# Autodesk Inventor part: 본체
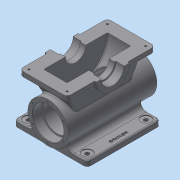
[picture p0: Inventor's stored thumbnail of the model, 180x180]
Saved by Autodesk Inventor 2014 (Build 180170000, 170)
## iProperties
Created: 2023-07
Part Number: 본체
Material: 일반
Document SubType Name: Modeling
Designer: dg
Density: 1 g/cm^3
Appearance: 기본값
Author: dg
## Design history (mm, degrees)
sketch "스케치1"
  geometry: L1 (-121, 0)-(121, 0); L2 (-121, 0)-(-121, 55); L3 (-121, 55)-(121, 55); L4 (121, 55)-(121, 0); L5 (-121, 42.5)-(-96, 42.5); L6 (-96, 42.5)-(-96, 38.5); L7 (-96, 38.5)-(96, 38.5); L8 (96, 38.5)-(96, 42.5); L9 (96, 42.5)-(121, 42.5); 2 further points
  constraints: 18 end point, 5 perpendicular, 3 parallel, 2 coincident, 2 point on line, 1 horizontal, 1 midpoint
  dimensions: "d0" = 242 distance of L1.start L1.end; "d1" = 110 diameter of L3 L1; "d2" = 85 diameter of L5 L1; "d3" = 77 diameter of L7 L1; "d4" = 85 diameter of L9 L1; "d5" = 25 distance between parallel lines of L4 L8; "d6" = 25 distance between parallel lines of L2 L6
revolve "회전1" sketch "스케치1" stored, may be unused: angle "d7" = 90 deg
node "작업 평면1"
sketch "스케치2"
  geometry: L1 (-100, -45)-(100, -45); L2 (100, -45)-(100, -60); L3 (100, -60)-(-100, -60); L4 (-100, -60)-(-100, -45); 2 further points
  constraints: 8 end point, 2 parallel, 1 horizontal, 1 midpoint, 1 perpendicular, 1 vertical alignment
  dimensions: "d9" = 60 distance from line of L3 point (0, 0); "d10" = 15 distance between parallel lines of L3 L1; "d11" = 200 distance between parallel lines of L2 L4
extrude "돌출1" join sketch "스케치2" stored distance "d12" = 200; taper "d13" = 0 deg
fillet "모깎기1" dims "d14" = 15
sketch "스케치3"
  geometry: L1 (-114, -60)-(86, -60) reference; L2 (-121, -55)-(-121, 55) reference; L3 (-114, 100)-(86, 100); L4 (86, -55)-(86, -60) reference; L5 (86, -60)-(-114, -60) reference; L6 (-114, -60)-(-114, -55) reference; L7 (-114, -55)-(-121, -55) reference; L8 (-121, -55)-(-121, -42.5) reference; L9 (-121, -42.5)-(-96, -42.5) reference; L10 (-96, -42.5)-(-96, -38.5) reference; L11 (-96, -38.5)-(96, -38.5) reference; L12 (96, -38.5)-(96, -42.5) reference; L13 (96, -42.5)-(121, -42.5) reference; L14 (121, -42.5)-(121, -55) reference; L15 (121, -55)-(86, -55) reference; L16 (-121, 55)-(121, 55) reference; L17 (121, 55)-(121, 42.5) reference; L18 (121, 42.5)-(96, 42.5) reference; L19 (96, 42.5)-(96, 38.5) reference; L20 (96, 38.5)-(-96, 38.5) reference; L21 (-96, 38.5)-(-96, 42.5) reference; L22 (-96, 42.5)-(-121, 42.5) reference; L23 (-121, 42.5)-(-121, 55) reference; A1 r 100 centre (-14, 100) between (-114, 100) and (86, 100); 2 further points
  constraints: 2 end point, 2 point on circle, 1 centre point, 1 coincident, 1 midpoint, 1 perpendicular
  dimensions: "d15" = 200 diameter of A1; "d16" = 160 distance from line of L1 A1.centre; "d17" = 107 distance from line of L2 A1.centre
extrude "돌출2" join sketch "스케치3" stored distance "d18" = 90; taper "d19" = 0 deg
sketch "스케치4"
  geometry: L1 (90, 200)-(90, 0) reference; L2 (0, 200)-(90, 200) reference; L3 (-20, 220)-(110, 220); L4 (110, 220)-(110, -20); L5 (110, -20)-(-20, -20); L6 (-20, -20)-(-20, 220); 5 further points
  constraints: 8 end point, 4 midpoint, 2 parallel, 1 horizontal, 1 horizontal alignment, 1 perpendicular, 1 vertical alignment
  dimensions: "d20" = 130 distance between parallel lines of L4 L6; "d21" = 240 distance between parallel lines of L5 L3
extrude "돌출3" join sketch "스케치4" distance "d22" = 15; taper "d23" = 0 deg
sketch "스케치5"
  geometry: L1 (-92.853, 38.5)-(-96, 38.5) reference; L2 (-96, 38.5)-(-96, 42.5) reference; L3 (-96, 42.5)-(-121, 42.5) reference; L4 (-121, 42.5)-(-121, 55) reference; L5 (-121, 55)-(-103.303, 55) reference; L6 (-112.869, 85)-(-134, 85) reference; L7 (-134, 85)-(-134, 100) reference; L8 (-134, 100)-(106, 100) reference; L9 (106, 100)-(106, 85) reference; L10 (106, 85)-(84.869, 85) reference; L11 (75.303, 55)-(121, 55) reference; L12 (121, 55)-(121, 42.5) reference; L13 (121, 42.5)-(96, 42.5) reference; L14 (96, 42.5)-(96, 38.5) reference; L15 (96, 38.5)-(64.853, 38.5) reference; L16 (86, -55)-(86, -60) reference; L17 (86, -60)-(-114, -60) reference; L18 (-114, -60)-(-114, -55) reference; L19 (-114, -55)-(-121, -55) reference; L20 (-121, -55)-(-121, -42.5) reference; L21 (-121, -42.5)-(-96, -42.5) reference; L22 (-96, -42.5)-(-96, -38.5) reference; L23 (-96, -38.5)-(96, -38.5) reference; L24 (96, -38.5)-(96, -42.5) reference; L25 (96, -42.5)-(121, -42.5) reference; L26 (121, -42.5)-(121, -55) reference; L27 (121, -55)-(86, -55) reference; C1 r 87 at (-14, 100); A1 r 100 centre (-14, 100) between (-92.853, 38.5) and (64.853, 38.5) reference; A2 r 100 centre (-14, 100) between (-112.869, 85) and (-103.303, 55) reference; A3 r 100 centre (-14, 100) between (75.303, 55) and (84.869, 85) reference; 1 further point
  constraints: 1 centre point, 1 coincident
  dimensions: "d24" = 87 radius of C1
  node "절단 모서리 투영2"
extrude "돌출4" cut sketch "스케치5" stored distance "d25" = 64; taper "d26" = 0 deg
sketch "스케치6"
  geometry: C1 r 38.5 at (0, 0) reference; C2 r 38.5 at (0, 0)
  constraints: 1 centre point, 1 coincident, 1 concentric
extrude "돌출5" cut sketch "스케치6" stored distance "d27" = 64; taper "d28" = 0 deg
sketch "스케치7"
  geometry: L1 (106, 85)-(84.869, 85) reference; L2 (75.303, 55)-(121, 55) reference; L3 (121, 55)-(121, 42.5) reference; L4 (121, 42.5)-(96, 42.5) reference; L5 (96, 42.5)-(96, 38.5) reference; L6 (96, 38.5)-(47.537, 38.5) reference; L7 (73, 100)-(106, 100) reference; L8 (106, 100)-(106, 85) reference; L9 (-112.869, 85)-(-134, 85) reference; L10 (-134, 85)-(-134, 100) reference; L11 (-134, 100)-(-101, 100) reference; L12 (-75.537, 38.5)-(-96, 38.5) reference; L13 (-96, 38.5)-(-96, 42.5) reference; L14 (-96, 42.5)-(-121, 42.5) reference; L15 (-121, 42.5)-(-121, 55) reference; L16 (-121, 55)-(-103.303, 55) reference; L17 (86, -55)-(86, -60) reference; L18 (86, -60)-(-114, -60) reference; L19 (-114, -60)-(-114, -55) reference; L20 (-114, -55)-(-121, -55) reference; L21 (-121, -55)-(-121, -42.5) reference; L22 (-121, -42.5)-(-96, -42.5) reference; L23 (-96, -42.5)-(-96, -38.5) reference; L24 (-96, -38.5)-(96, -38.5) reference; L25 (96, -38.5)-(96, -42.5) reference; L26 (96, -42.5)-(121, -42.5) reference; L27 (121, -42.5)-(121, -55) reference; L28 (121, -55)-(86, -55) reference; L29 (-101, 100)-(73, 100) reference; L30 (-59, 100)-(31, 100); A1 r 100 centre (-14, 100) between (75.303, 55) and (84.869, 85) reference; A2 r 87 centre (-14, 100) between (47.537, 38.5) and (73, 100) reference; A3 r 87 centre (-14, 100) between (-101, 100) and (-75.537, 38.5) reference; A4 r 100 centre (-14, 100) between (-112.869, 85) and (-103.303, 55) reference; A5 r 45 centre (-14, 100) between (-59, 100) and (31, 100); 3 further points
  constraints: 3 coincident, 2 end point, 2 midpoint, 2 point on circle, 1 centre point, 1 collinear
  dimensions: "d29" = 90 diameter of A5
extrude "돌출6" join sketch "스케치7" stored distance "d30" = 140; taper "d31" = 0 deg
extrude "돌출7" cut sketch "스케치5" stored distance "d32" = 64; taper "d33" = 0 deg
hole "구멍1" diameter "d36" = 55; stored, may be unused: countersink angle "d40" = 90 deg, drill point angle "d42" = 118 deg; dims "d34" = 10, "d35" = 10, "d37" = 6, "d38" = 62, "d39" = 23, "d41" = 65.75
fillet "모깎기2" dims "d43" = 10
sketch "스케치8"
  geometry: L1 (-15, 56)-(-38, 56) reference; L2 (-38, 132)-(-33, 132) reference; L3 (-33, 132)-(-33, 197) reference; L4 (-23, 207)-(87, 207) reference; L5 (97, 197)-(97, 132) reference; L6 (97, 132)-(102, 132) reference; L7 (102, 132)-(102, 118) reference; L8 (102, 118)-(79, 118) reference; L9 (79, 118)-(79, 114.5) reference; L10 (79, 114.5)-(64, 114.5) reference; L11 (64, 114.5)-(64, 174) reference; L12 (64, 174)-(0, 174) reference; L13 (0, 174)-(0, 114.5) reference; L14 (0, 114.5)-(-15, 114.5) reference; L15 (-15, 114.5)-(-15, 118) reference; L16 (-15, 118)-(-38, 118) reference; L17 (-38, 118)-(-38, 132) reference; L18 (102, 42)-(97, 42) reference; L19 (97, 42)-(97, -23) reference; L20 (87, -33)-(-23, -33) reference; L21 (-33, -23)-(-33, 42) reference; L22 (-33, 42)-(-38, 42) reference; L23 (-38, 42)-(-38, 56) reference; L24 (-38, 56)-(-15, 56) reference; L25 (-15, 56)-(-15, 59.5) reference; L26 (-15, 59.5)-(0, 59.5) reference; L27 (0, 59.5)-(0, 0) reference; L28 (0, 0)-(64, 0) reference; L29 (64, 0)-(64, 59.5) reference; L30 (64, 59.5)-(79, 59.5) reference; L31 (79, 59.5)-(79, 56) reference; L32 (79, 56)-(102, 56) reference; L33 (102, 56)-(102, 42) reference; L34 (-15, 59.5)-(-15, 114.5) reference; A1 r 10 centre (-23, 197) between (-23, 207) and (-33, 197) reference; A2 r 10 centre (87, 197) between (97, 197) and (87, 207) reference; A3 r 10 centre (87, -23) between (87, -33) and (97, -23) reference; A4 r 10 centre (-23, -23) between (-33, -23) and (-23, -33) reference; 4 further points
  constraints: 1 coincident, 1 midpoint
  dimensions: "d44" = 52 horizontal distance of point (32, 101) point (-20, -20); "d46" = 31 distance from line of point (-15, 87) L1; "d47" = 107 vertical distance of point (-20, -20) point (-15, 87)
hole "구멍2" sketch "스케치8" at (-20, -20) diameter "d48" = 4.917; stored, may be unused: countersink angle "d52" = 90 deg, drill point angle "d54" = 118 deg; dims "d49" = 30, "d50" = 4, "d51" = 2, "d53" = 32.5
node "작업 평면2"
sketch "스케치9" dims "d56" = 74
  geometry: L1 (-100, -14)-(-55, -14); L2 (-100, -14)-(-68.18, -45.82); A1 r 45 centre (-100, -14) between (-100, -59) and (-100, 31) reference; 3 further points
  constraints: 4 end point, 2 point on circle, 1 coincident, 1 point on line, 3 other
  dimensions: "d55" = 45 deg angle of L1 L2
hole "구멍3" sketch "스케치9" at (-73.837, -40.163) diameter "d57" = 4.134; stored, may be unused: countersink angle "d61" = 90 deg, drill point angle "d63" = 118 deg; dims "d58" = 10, "d59" = 4, "d60" = 2, "d62" = 12
sketch "스케치10"
  geometry: C1 r 55 at (0, 0) reference; 1 further point
  constraints: 1 vertical alignment
  dimensions: "d64" = 48.5 distance of C1.centre point (0, 48.5)
hole "구멍4" sketch "스케치10" at (0, 48.5) diameter "d65" = 4.134; stored, may be unused: countersink angle "d69" = 90 deg, drill point angle "d71" = 118 deg; dims "d66" = 10, "d67" = 4, "d68" = 2, "d70" = 12
node "작업 평면3"
fillet "모깎기3" dims "d75" = 10
sketch "스케치11"
  geometry: L1 (-26.754, 200)-(0, 200) reference; L2 (-36.754, 190)-(-36.754, 10) reference; L3 (31.623, 0)-(0, 0) reference; L4 (0, 0)-(-26.754, 0) reference; L5 (-36.754, 10)-(-36.754, 190) reference; L6 (-26.754, 200)-(0, 200) reference; L7 (0, 0)-(0, 200) reference; L8 (31.623, -7)-(31.623, 0) reference; L9 (94.868, -7)-(31.623, -7) reference; L10 (94.868, 0)-(94.868, -7) reference; L11 (126.491, 0)-(94.868, 0) reference; L12 (126.491, 200)-(126.491, 0) reference; L13 (94.868, 200)-(126.491, 200) reference; L14 (94.868, 235)-(94.868, 200) reference; L15 (31.623, 235)-(94.868, 235) reference; L16 (31.623, 200)-(31.623, 235) reference; L17 (0, 200)-(31.623, 200) reference; L18 (153.246, 0)-(126.491, 0) reference; L19 (163.246, 190)-(163.246, 10) reference; L20 (126.491, 200)-(153.246, 200) reference; A1 r 10 centre (-26.754, 10) between (-36.754, 10) and (-26.754, 0) reference; A2 r 10 centre (-26.754, 190) between (-26.754, 200) and (-36.754, 190) reference; A3 r 10 centre (153.246, 10) between (153.246, 0) and (163.246, 10) reference; A4 r 10 centre (153.246, 190) between (163.246, 190) and (153.246, 200) reference; 3 further points
  constraints: 1 midpoint
  dimensions: "d76" = 100 distance from line of L1 point (-36.754, 100); "d77" = 80 vertical distance of point (-36.754, 100) point (-16.754, 180); "d78" = 80 horizontal distance of point (-16.754, 180) point (63.246, 114)
hole "구멍5" sketch "스케치11" at (-16.754, 180) diameter "d79" = 11; stored, may be unused: countersink angle "d83" = 90 deg, drill point angle "d85" = 118 deg; dims "d80" = 10, "d81" = 28, "d82" = 2, "d84" = 19.25
node "작업 평면4"
fillet "모깎기4" dims "d86" = 1.1
fillet "모깎기5" dims "d87" = 3
fillet "모깎기6" dims "d88" = 3
fillet "모깎기7" dims "d89" = 3
fillet "모깎기8" dims "d90" = 3
chamfer "모따기1" distance "d91" = 1; stored, may be unused: second distance "d92" = 2, angle "d93" = 45 deg
chamfer "모따기2" distance "d94" = 1; stored, may be unused: second distance "d95" = 2, angle "d96" = 45 deg
fillet "모깎기9" dims "d97" = 1
fillet "모깎기10" dims "d98" = 3
fillet "모깎기11" dims "d99" = 3
fillet "모깎기12" dims "d100" = 3
fillet "모깎기13" dims "d101" = 3
sketch "스케치12"
  geometry: L1 (5.754, -66)-(5.754, -128) reference; L2 (36.754, -187)-(36.754, -7) reference; 3 further points
  constraints: 1 horizontal alignment, 1 midpoint, 1 other
  dimensions: "d102" = 15 distance from line of L2 point (21.754, -97)
feature "엠보싱1" sketch "스케치12" dims "d9" = 60, "d10" = 15, "d11" = 200, "d103" = 0.5, "d104" = 0
fillet "모깎기14" dims "d105" = 3
fillet "모깎기15" dims "d106" = 3
fillet "모깎기16" dims "d107" = 3
fillet "모깎기17" dims "d108" = 3
node "솔리드1"
mirror "대칭1"
mirror "대칭2"
mirror "대칭3"
mirror "대칭4"
mirror "대칭5"
pattern_circular "원형 패턴1" dims angle "d73" = 360 deg
mirror "대칭6"
mirror "대칭7"
mirror "대칭8"
node "절단 모서리 투영1"
node "절단 모서리 투영3"
node "절단 모서리 투영4"
node "절단 모서리 투영5"
other parameters: "d8" = -107
